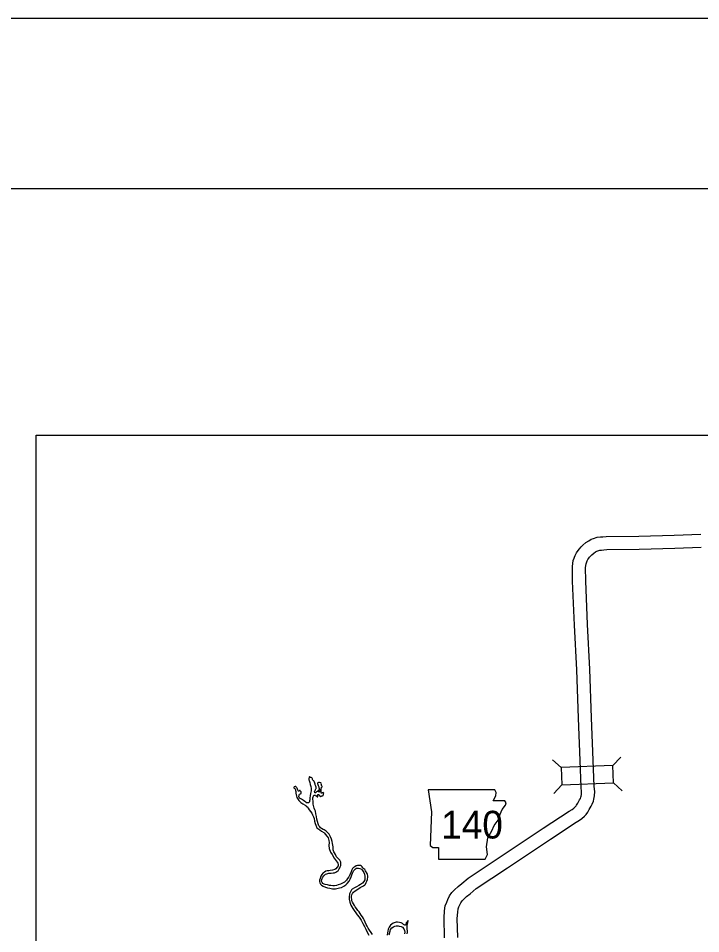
# Model space of a CAD drawing. Extents: x -117616 to 64730, y 54117 to 789866.
# Drawn here: x 61552.5 to 61708.6, y 56041.5 to 56250.9 of the extents above; entities that cross this region are included whole.
import ezdxf

# ---------------------------------------------------------------- set-up
doc = ezdxf.new("R2010")
doc.units = 0
for name, color, linetype in [('Level 10', 7, 'Continuous'), ('Level 20', 7, 'Continuous'), ('Level 21', 7, 'Continuous'), ('Level 9', 7, 'Continuous'), ('R_Border', 7, 'Continuous'), ('R_No Plot', 7, 'Continuous')]:
    doc.layers.add(name, color=color, linetype=linetype)

msp = doc.modelspace()

# ---------------------------------------------------------------- linework, layer by layer
at = {"layer": 'Level 10'}
for points in [[(61650.01, 56040.58), (61649.88, 56045.13), (61650.02, 56046.73), (61650.14, 56047.92), (61650.49, 56048.78), (61650.74, 56049.39), (61651.16, 56050.17), (61651.7, 56050.93), (61652.28, 56051.54), (61653.09, 56052.32), (61653.94, 56052.99), (61655.44, 56054.27), (61662.72, 56059.08), (61672.59, 56065.68), (61678.53, 56069.58), (61679.18, 56069.97), (61679.55, 56070.24), (61679.97, 56070.6), (61680.13, 56070.76), (61680.22, 56070.89), (61680.48, 56071.41), (61680.9, 56072.13), (61681.07, 56072.45), (61681.21, 56072.79), (61681.26, 56072.97), (61681.33, 56073.38), (61681.35, 56074.01), (61681.27, 56075.06), (61681.04, 56081.11), (61680.65, 56090.79), (61680.23, 56101.87), (61679.72, 56112.11), (61679.31, 56122.14), (61679.24, 56125.47), (61679.46, 56126.88), (61679.63, 56127.38), (61679.74, 56127.67), (61679.9, 56128.05), (61680.17, 56128.62), (61680.58, 56129.19), (61680.87, 56129.56), (61681.26, 56129.99), (61681.63, 56130.37), (61682.36, 56130.99), (61683.02, 56131.41), (61683.58, 56131.73), (61684.1, 56131.92), (61684.92, 56132.19), (61685.7, 56132.26), (61686.25, 56132.3), (61686.98, 56132.36), (61694.45, 56132.45), (61702.56, 56132.67), (61708.61, 56132.9)], [(61653.01, 56040.67), (61652.88, 56045.04), (61653.01, 56046.45), (61653.08, 56047.19), (61653.27, 56047.65), (61653.46, 56048.1), (61653.72, 56048.58), (61654.03, 56049.02), (61654.42, 56049.43), (61655.06, 56050.06), (61655.84, 56050.67), (61657.24, 56051.87), (61664.38, 56056.58), (61674.25, 56063.18), (61680.11, 56067.04), (61680.86, 56067.47), (61681.42, 56067.9), (61682, 56068.39), (61682.43, 56068.82), (61682.79, 56069.34), (61683.12, 56069.97), (61683.53, 56070.69), (61683.79, 56071.19), (61684.05, 56071.81), (61684.19, 56072.3), (61684.32, 56073.07), (61684.35, 56074.07), (61684.27, 56075.22), (61684.03, 56081.23), (61683.65, 56090.91), (61683.23, 56102), (61682.71, 56112.24), (61682.31, 56122.23), (61682.24, 56125.27), (61682.38, 56126.15), (61682.46, 56126.37), (61682.53, 56126.57), (61682.64, 56126.82), (61682.77, 56127.09), (61682.98, 56127.39), (61683.16, 56127.62), (61683.44, 56127.93), (61683.68, 56128.18), (61684.14, 56128.57), (61684.57, 56128.84), (61684.85, 56129), (61685.08, 56129.08), (61685.54, 56129.23), (61685.93, 56129.27), (61686.48, 56129.3), (61687.12, 56129.36), (61694.51, 56129.45), (61702.66, 56129.67), (61708.72, 56129.9)]]:
    msp.add_lwpolyline(points, dxfattribs=at)
at = {"layer": 'Level 20'}
for p, q in [((61676.66, 56079.52), (61674.72, 56081.31)), ((61688.53, 56079.99), (61690.32, 56081.93)), ((61676.81, 56075.57), (61675.02, 56073.63)), ((61688.68, 56076.03), (61690.62, 56074.24))]:
    msp.add_line(p, q, dxfattribs=at)
msp.add_lwpolyline([(61688.53, 56079.99), (61676.66, 56079.52), (61676.81, 56075.57), (61688.68, 56076.03)], close=True, dxfattribs=at)
at = {"layer": 'Level 21'}
msp.add_lwpolyline([(61646.25, 56074.44), (61647.01, 56069.37), (61646.68, 56061.67), (61647.35, 56061.25), (61648.62, 56061.25), (61648.62, 56058.54), (61659.28, 56058.54), (61659.79, 56059.64), (61659.62, 56061.42), (61659.87, 56063.45), (61660.8, 56065.05), (61661.39, 56066.24), (61662.24, 56067.51), (61662.75, 56068.86), (61663.17, 56069.96), (61663.93, 56070.89), (61664.1, 56071.48), (61663.76, 56071.91), (61661.14, 56071.91), (61661.73, 56073.09), (61661.82, 56073.85), (61661.47, 56074.44)], close=True, dxfattribs=at)
at = {"layer": 'Level 9'}
for points in [[(61621.43, 56073.97), (61621.4, 56073.94), (61621.31, 56073.89), (61621.28, 56073.91), (61621.24, 56074), (61621.22, 56074.11), (61621.21, 56074.19), (61621.21, 56074.22), (61621.18, 56074.3), (61621.18, 56074.32), (61621.16, 56074.35), (61621.13, 56074.36), (61621.1, 56074.33), (61621.07, 56074.28), (61621.03, 56074.19), (61620.98, 56074.09), (61620.93, 56074.04), (61620.69, 56073.94), (61620.54, 56073.84), (61620.52, 56073.81), (61620.44, 56073.76), (61620.32, 56073.78), (61620.29, 56073.84), (61620.26, 56073.98), (61620.33, 56074.2), (61620.38, 56074.31), (61620.47, 56074.48), (61620.57, 56074.67), (61620.6, 56074.76), (61620.61, 56074.9), (61620.61, 56075.07), (61620.54, 56075.27), (61620.42, 56075.57), (61620.37, 56075.76), (61620.3, 56075.98), (61620.19, 56076.35), (61620.06, 56076.49), (61619.96, 56076.56), (61619.87, 56076.66), (61619.82, 56076.83), (61619.76, 56076.98), (61619.7, 56077.07), (61619.61, 56077.16), (61619.48, 56077.23), (61619.35, 56077.29), (61619.25, 56077.34), (61619.13, 56077.42), (61619.05, 56077.38), (61619.01, 56077.3), (61619.01, 56077.2), (61618.98, 56076.99), (61618.95, 56076.82), (61618.96, 56076.7), (61619, 56076.53), (61619.09, 56076.33), (61619.2, 56076.08), (61619.27, 56075.69), (61619.38, 56075.16), (61619.46, 56074.77), (61619.48, 56074.44), (61619.47, 56074.19), (61619.44, 56073.93), (61619.35, 56073.6), (61619.22, 56073.06), (61619.17, 56072.57), (61619.15, 56072.16), (61619.13, 56071.88), (61619.08, 56071.69), (61619.03, 56071.58), (61618.93, 56071.47), (61618.88, 56071.44), (61618.77, 56071.43), (61618.45, 56071.48), (61618.26, 56071.64), (61618.05, 56071.8), (61617.75, 56071.97), (61617.47, 56072.14), (61617.27, 56072.32), (61617.13, 56072.39), (61617, 56072.46), (61616.82, 56072.54), (61616.73, 56072.74), (61616.69, 56072.87), (61616.69, 56072.99), (61616.71, 56073.17), (61616.74, 56073.29), (61616.84, 56073.43), (61617.01, 56073.54), (61617.16, 56073.63), (61617.21, 56073.71), (61617.21, 56073.81), (61617.21, 56073.9), (61617.19, 56073.99), (61617.13, 56074.06), (61617.05, 56074.12), (61616.99, 56074.2), (61616.94, 56074.27), (61616.86, 56074.31), (61616.82, 56074.29), (61616.76, 56074.23), (61616.69, 56074.16)], [(61616.69, 56074.16), (61616.63, 56074.15), (61616.58, 56074.16), (61616.5, 56074.22), (61616.43, 56074.36), (61616.36, 56074.6), (61616.28, 56074.81), (61616.15, 56075), (61616.04, 56075.12), (61615.96, 56075.17), (61615.91, 56075.2), (61615.81, 56075.19), (61615.61, 56075.11), (61615.54, 56075), (61615.53, 56074.9), (61615.58, 56074.82), (61615.73, 56074.7), (61615.81, 56074.62), (61615.88, 56074.47), (61615.92, 56074.27), (61615.94, 56074.05), (61615.95, 56073.68), (61616.1, 56072.95), (61616.24, 56072.65), (61616.51, 56072.2), (61616.67, 56071.98), (61616.85, 56071.82), (61617.14, 56071.55), (61617.61, 56071.26), (61618.11, 56070.94), (61618.25, 56070.82), (61618.37, 56070.72), (61618.55, 56070.57), (61618.77, 56070.24), (61619.05, 56069.83), (61619.62, 56069.1), (61619.81, 56068.74), (61620.01, 56068.26), (61620.14, 56067.86), (61620.26, 56067.3), (61620.36, 56066.76), (61620.52, 56066.32), (61620.81, 56065.77), (61620.99, 56065.57), (61621.44, 56065.26), (61621.88, 56065.01), (61622.36, 56064.7), (61622.5, 56064.56), (61622.7, 56064.28), (61623.17, 56063.74), (61623.34, 56063.43), (61623.43, 56063.18), (61623.56, 56062.81), (61623.62, 56062.38), (61623.55, 56061.69), (61623.63, 56060.98), (61623.92, 56060.2), (61624.27, 56059.62), (61624.74, 56058.82), (61624.95, 56058.48), (61625.2, 56058.17), (61625.45, 56057.87), (61625.58, 56057.63), (61625.66, 56057.35), (61625.65, 56057.03), (61625.45, 56056.71), (61625.15, 56056.37), (61624.89, 56056.18), (61624.38, 56056.04), (61623.84, 56055.96), (61623.56, 56055.92), (61623.11, 56055.9), (61622.84, 56055.8), (61622.53, 56055.6), (61622.24, 56055.42), (61621.92, 56055.08), (61621.7, 56054.66), (61621.51, 56054.16), (61621.39, 56053.81), (61621.42, 56053.47), (61621.5, 56053.2), (61621.62, 56052.88), (61621.81, 56052.64), (61622.24, 56052.38), (61622.77, 56052.18), (61623.2, 56052.05), (61623.77, 56051.91), (61624.37, 56051.82), (61625.02, 56051.81), (61625.38, 56051.84), (61625.98, 56052), (61626.41, 56052.13), (61626.94, 56052.37), (61627.43, 56052.74), (61627.73, 56053.04), (61628.15, 56053.58), (61628.41, 56054.04), (61628.64, 56054.56), (61628.77, 56054.97), (61628.92, 56055.4), (61629.15, 56055.83)], [(61619.87, 56072.58), (61619.91, 56072.81), (61619.98, 56072.97), (61620.04, 56073.05), (61620.11, 56073.16), (61620.16, 56073.22), (61620.24, 56073.23), (61620.39, 56073.24), (61620.47, 56073.19), (61620.58, 56073.09), (61620.63, 56073.03), (61620.68, 56072.98), (61620.75, 56072.91), (61620.85, 56072.85), (61620.92, 56072.83), (61620.96, 56072.84), (61621, 56072.86), (61621.04, 56072.92), (61621.04, 56073.04), (61621.03, 56073.13), (61620.99, 56073.18), (61620.96, 56073.23), (61620.96, 56073.24), (61620.99, 56073.33), (61621.01, 56073.35), (61621.03, 56073.37), (61621.05, 56073.38), (61621.12, 56073.39), (61621.21, 56073.35), (61621.25, 56073.31), (61621.33, 56073.21), (61621.46, 56073.05), (61621.5, 56072.99), (61621.55, 56072.94), (61621.57, 56072.94), (61621.59, 56072.94), (61621.64, 56072.95), (61621.66, 56072.96), (61621.73, 56072.98), (61621.83, 56073.01), (61621.84, 56073.01), (61621.92, 56073.03), (61622.06, 56073.08), (61622.09, 56073.09), (61622.16, 56073.1), (61622.21, 56073.12), (61622.22, 56073.12), (61622.26, 56073.23), (61622.27, 56073.3), (61622.33, 56073.46), (61622.34, 56073.52), (61622.35, 56073.65), (61622.33, 56073.71), (61622.31, 56073.75), (61622.28, 56073.79), (61622.18, 56073.78), (61622.11, 56073.74), (61622.03, 56073.71), (61621.95, 56073.67), (61621.87, 56073.67), (61621.81, 56073.68), (61621.79, 56073.7), (61621.78, 56073.76), (61621.79, 56073.92), (61621.74, 56074.2), (61621.74, 56074.37), (61621.76, 56074.48), (61621.77, 56074.62), (61621.78, 56074.74), (61621.82, 56074.91), (61621.85, 56075.01), (61621.91, 56075.07), (61621.98, 56075.11), (61622.02, 56075.13), (61622.03, 56075.21), (61621.96, 56075.32), (61621.88, 56075.46), (61621.82, 56075.58), (61621.8, 56075.68), (61621.81, 56075.8), (61621.74, 56075.95), (61621.73, 56075.98), (61621.69, 56076.02), (61621.6, 56076.07), (61621.36, 56076.11), (61621.16, 56076.09), (61621.01, 56076.04), (61620.96, 56075.99), (61620.95, 56075.87), (61620.98, 56075.69), (61621.07, 56075.4), (61621.2, 56075.09), (61621.27, 56074.94), (61621.34, 56074.75), (61621.42, 56074.51), (61621.45, 56074.41), (61621.46, 56074.32), (61621.48, 56074.24), (61621.45, 56074.12), (61621.44, 56074.03), (61621.43, 56073.97)], [(61632.1, 56053.23), (61632.25, 56053.57), (61632.35, 56053.91), (61632.46, 56054.5), (61632.43, 56054.78), (61632.38, 56055.06), (61632.31, 56055.32), (61631.92, 56055.92), (61631.74, 56056.18), (61631.56, 56056.38), (61631.3, 56056.62), (61631.15, 56056.82), (61630.99, 56056.99), (61630.78, 56057.11), (61630.41, 56057.16), (61630.06, 56057.14), (61629.76, 56057.03), (61629.44, 56056.85), (61629.14, 56056.66), (61628.91, 56056.41), (61628.77, 56056.11), (61628.63, 56055.7), (61628.31, 56055.02), (61628.07, 56054.57), (61627.82, 56054.17), (61627.53, 56053.75), (61627.09, 56053.32), (61626.67, 56053.07), (61626.19, 56052.86), (61625.64, 56052.67), (61625.27, 56052.57), (61624.85, 56052.49), (61624.46, 56052.48), (61623.98, 56052.52), (61623.66, 56052.58), (61623.2, 56052.67), (61622.72, 56052.77), (61622.43, 56052.85), (61622.13, 56053.03), (61621.98, 56053.21), (61621.88, 56053.55), (61621.9, 56053.93), (61621.97, 56054.17), (61622.13, 56054.48), (61622.38, 56054.77), (61622.58, 56054.97), (61622.78, 56055.12), (61623.1, 56055.24), (61623.5, 56055.34), (61624.06, 56055.38), (61624.53, 56055.43), (61624.84, 56055.48), (61625.14, 56055.59), (61625.37, 56055.72), (61625.63, 56055.93), (61625.92, 56056.33), (61626.06, 56056.58), (61626.15, 56056.81), (61626.25, 56057.13), (61626.28, 56057.45), (61626.24, 56057.9), (61626.04, 56058.35), (61625.75, 56058.66), (61625.51, 56058.88), (61625.28, 56059.13), (61625.03, 56059.62), (61624.81, 56059.99), (61624.67, 56060.25), (61624.55, 56060.72), (61624.5, 56061.07), (61624.48, 56061.43), (61624.39, 56062.16), (61624.28, 56062.61), (61624.12, 56063.16), (61623.91, 56063.71), (61623.57, 56064.26), (61623.32, 56064.59), (61622.95, 56064.96), (61622.66, 56065.17), (61622.43, 56065.28), (61622.2, 56065.38), (61621.87, 56065.57), (61621.62, 56065.77), (61621.47, 56065.94), (61621.27, 56066.21), (61621.14, 56066.42), (61621.11, 56066.64), (61620.96, 56067.18), (61620.81, 56067.72), (61620.68, 56068.37), (61620.56, 56068.95), (61620.44, 56069.53), (61620.31, 56069.88), (61620.19, 56070.22), (61620.09, 56070.54), (61620.01, 56070.86), (61619.95, 56071.16), (61619.93, 56071.46), (61619.91, 56071.94), (61619.89, 56072.22), (61619.87, 56072.58)], [(61629.15, 56055.83), (61629.28, 56056.01), (61629.48, 56056.23), (61629.63, 56056.39), (61629.84, 56056.51), (61630.04, 56056.53), (61630.34, 56056.53), (61630.64, 56056.47), (61630.97, 56056.28), (61631.2, 56055.99), (61631.5, 56055.55), (61631.66, 56055.12), (61631.76, 56054.64), (61631.78, 56054.2), (61631.75, 56053.84), (61631.5, 56053.47), (61631.21, 56053.12), (61630.8, 56052.78), (61630.39, 56052.55), (61629.88, 56052.28), (61629.39, 56052.02), (61628.88, 56051.68), (61628.71, 56051.53), (61628.28, 56050.65), (61628.21, 56049.9), (61628.21, 56049.41), (61628.35, 56048.72), (61628.57, 56048.08), (61629.03, 56047.31), (61630.03, 56045.85), (61630.45, 56045.35), (61630.94, 56044.62), (61631.34, 56043.83), (61631.7, 56043.16), (61631.97, 56042.58), (61632.37, 56041.73), (61632.66, 56041.17)], [(61633.55, 56041.33), (61633.19, 56041.81), (61632.86, 56042.32), (61632.55, 56042.83), (61632.26, 56043.26), (61632.08, 56043.63), (61631.81, 56044.19), (61631.58, 56044.72), (61631.46, 56045.01), (61631.21, 56045.41), (61630.94, 56045.76), (61630.43, 56046.51), (61630.17, 56046.83), (61629.84, 56047.29), (61629.58, 56047.65), (61629.38, 56047.98), (61629.15, 56048.33), (61628.93, 56048.78), (61628.82, 56049.04), (61628.75, 56049.41), (61628.72, 56049.76), (61628.72, 56050.11), (61628.78, 56050.45), (61628.92, 56050.72), (61629.13, 56051.03), (61629.58, 56051.36), (61630.14, 56051.71), (61630.71, 56052.06), (61631.12, 56052.29), (61631.45, 56052.48), (61631.74, 56052.7), (61631.9, 56052.89), (61632.1, 56053.23)], [(61641.42, 56041.47), (61641.51, 56041.86), (61641.54, 56042.21), (61641.47, 56042.56), (61641.45, 56042.8), (61641.42, 56043.08), (61641.41, 56043.28), (61641.43, 56043.59), (61641.59, 56044.08), (61641.68, 56044.38), (61641.7, 56044.49), (61641.67, 56044.54), (61641.35, 56044.18), (61641.25, 56044), (61641.18, 56043.81), (61641.15, 56043.71), (61641.11, 56043.59), (61641.02, 56043.49), (61640.91, 56043.47), (61640.62, 56043.62), (61640.35, 56043.83), (61640.07, 56044), (61639.7, 56044.12), (61639.25, 56044.16), (61638.91, 56044.15), (61638.68, 56044.12), (61638.23, 56043.95), (61637.91, 56043.73), (61637.63, 56043.5), (61637.34, 56043.05), (61637.12, 56042.59), (61636.99, 56042.12), (61636.94, 56041.7), (61636.9, 56041.22)], [(61637.33, 56041.28), (61637.57, 56042.1), (61637.67, 56042.46), (61637.96, 56042.84), (61638.29, 56043.08), (61638.66, 56043.24), (61638.96, 56043.34), (61639.36, 56043.31), (61639.65, 56043.29), (61640.09, 56043.19), (61640.36, 56043.01), (61640.65, 56042.67), (61640.82, 56042.3), (61640.88, 56041.88), (61640.83, 56041.5)]]:
    msp.add_lwpolyline(points, dxfattribs=at)
at = {"layer": 'R_Border'}
msp.add_line((61520.24, 56211.92), (64682.04, 56211.92), dxfattribs=at)
at = {"layer": 'R_No Plot'}
msp.add_line((61396.23, 56250.87), (64729.56, 56250.87), dxfattribs=at)
for points in [[(61396.16, 56250.87), (64729.56, 56250.87), (64729.56, 54117.5), (61396.16, 54117.5)], [(61556.57, 56155.54), (62285.97, 56155.54), (62285.97, 55371.05), (61556.57, 55371.05)]]:
    msp.add_lwpolyline(points, close=True, dxfattribs=at)

# ---------------------------------------------------------------- texts
at = {"layer": 'Level 21'}
msp.add_text('140', height=6.336, dxfattribs=at).set_placement((61649.21, 56063.3))

doc.saveas('drawing.dxf')
